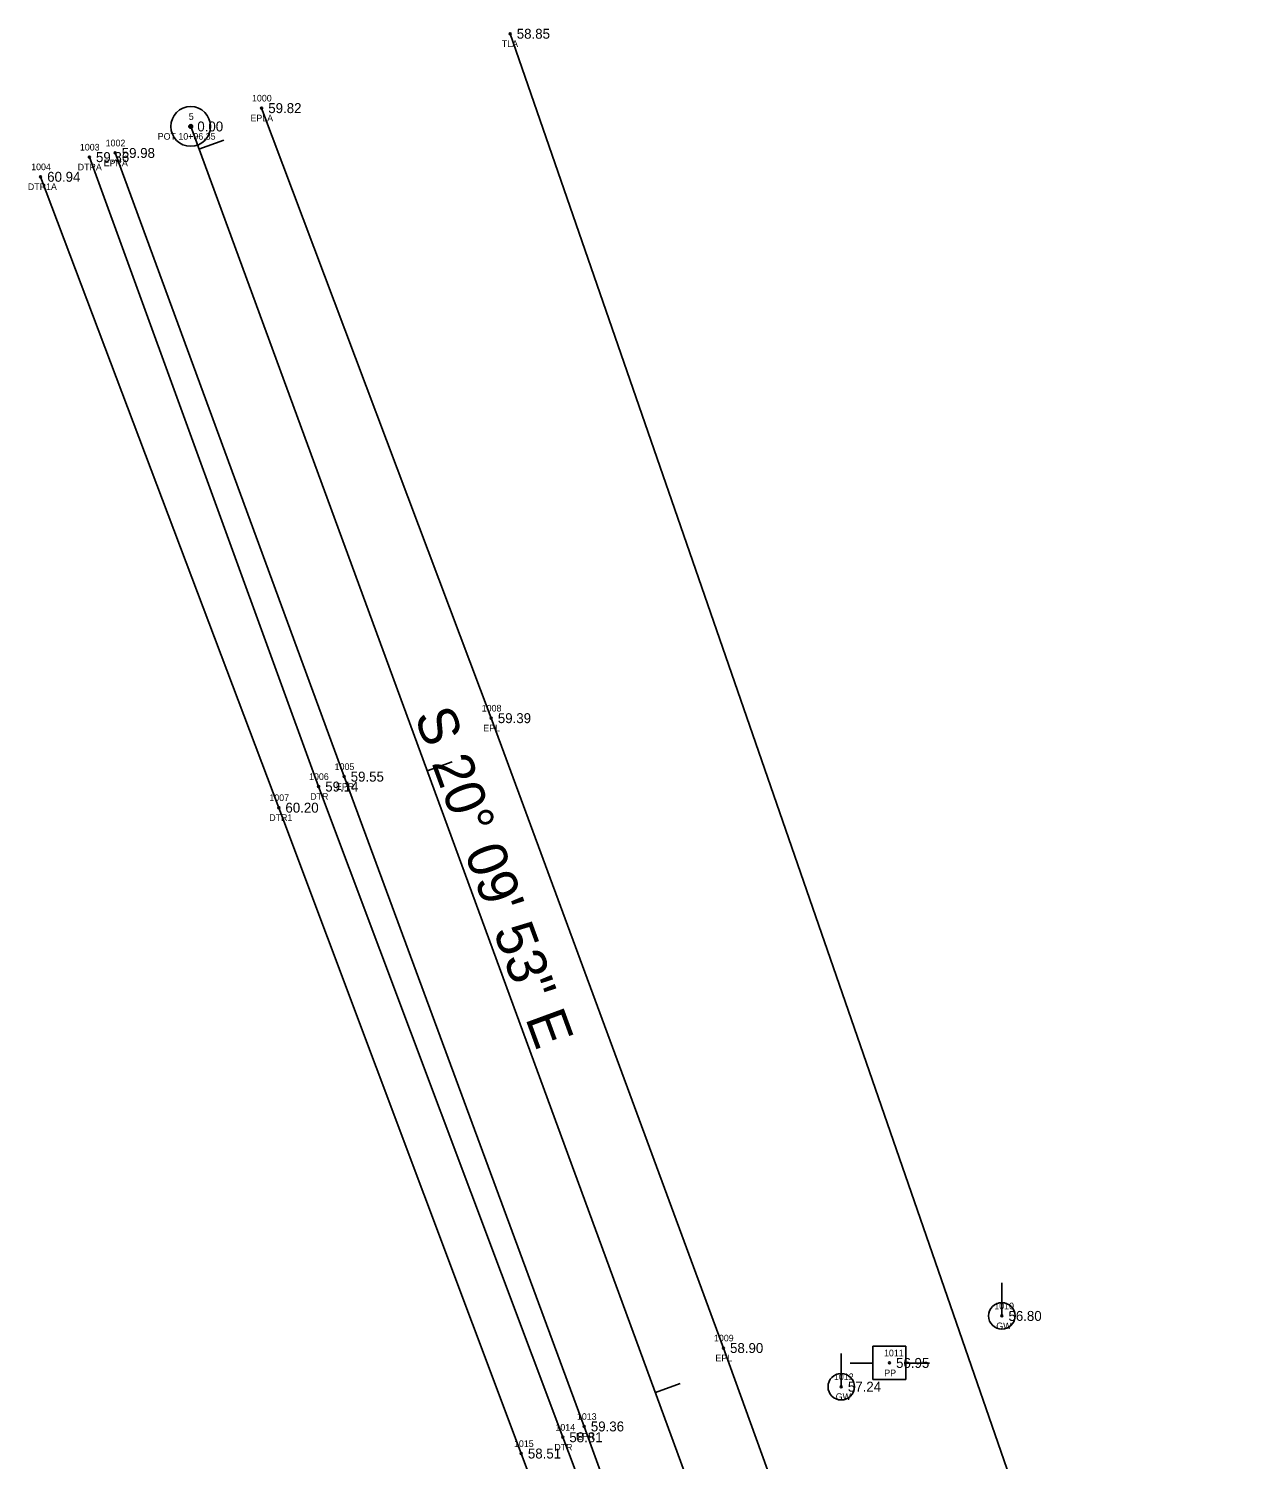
# Model space of a CAD drawing. Extents: x 2396531 to 2397633, y 770203 to 772837.
# Drawn here: x 2396645.7 to 2396831.5, y 772413.8 to 772629.8 of the extents above; entities that cross this region are included whole.
import ezdxf

# ---------------------------------------------------------------- set-up
doc = ezdxf.new("R2010")
doc.units = 0
for name, color, linetype in [('RD_EX_H2O', 7, 'Continuous'), ('RD_EX_H2O_txCode', 7, 'Continuous'), ('RD_EX_Road', 7, 'Continuous'), ('RD_EX_Road_txCode', 7, 'Continuous'), ('RD_EX_TX_H2O_ELEV', 7, 'Continuous'), ('RD_EX_TX_Road_ELEV', 7, 'Continuous'), ('RD_EX_TX_UT_ELEV', 7, 'Continuous'), ('RD_EX_TX_VEG_ELEV', 7, 'Continuous'), ('RD_EX_UT', 7, 'Continuous'), ('RD_EX_UT_txCode', 7, 'Continuous'), ('RD_EX_VEG', 7, 'Continuous'), ('RD_EX_VEG_txCode', 7, 'Continuous'), ('RD_HC_Cl', 7, 'Continuous'), ('RD_HC_Data', 7, 'Continuous'), ('RD_HC_Data_Tic', 7, 'Continuous'), ('RD_HC_Survey_ELEV', 7, 'Continuous'), ('RD_HC_txCode', 7, 'Continuous'), ('RD_SMD_Locator', 7, 'Continuous')]:
    doc.layers.add(name, color=color, linetype=linetype)

msp = doc.modelspace()

# ---------------------------------------------------------------- linework, layer by layer
at = {"layer": 'RD_EX_H2O'}
for points in [[(2396654.89, 772610.44), (2396689.53, 772515.4), (2396726.4, 772417.15), (2396758.49, 772332.26), (2396786.59, 772254.26)], [(2396647.52, 772607.47), (2396683.51, 772512.21), (2396720.14, 772414.69), (2396752.02, 772329.6), (2396778.94, 772251.31)]]:
    msp.add_lwpolyline(points, dxfattribs=at)
at = {"layer": 'RD_EX_Road'}
for points in [[(2396680.92, 772617.84), (2396715.6, 772525.73), (2396750.68, 772430.62), (2396786.3, 772332.21), (2396811.38, 772263.31), (2396839.69, 772181.74), (2396863.75, 772109.83), (2396883.63, 772046.56), (2396889.54, 772027.11), (2396896.25, 772004.37), (2396904.34, 771978.33), (2396908.24, 771964.89), (2396921.74, 771919.68), (2396927.03, 771902.11), (2396950.2, 771821.74), (2396970.47, 771750.68), (2396978.33, 771721.29), (2396990.58, 771675.04), (2397004.94, 771620.49), (2397034.26, 771508.8), (2397061.11, 771410.49), (2397060.64, 771407.04), (2397062.07, 771407.67)], [(2396658.78, 772611.07), (2396693.37, 772516.9), (2396729.65, 772418.78), (2396760.7, 772333.11), (2396788.58, 772254.87), (2396814.65, 772181.57), (2396841.1, 772100.86), (2396861.19, 772037.76), (2396886.09, 771955.71), (2396907.15, 771884.49), (2396928.56, 771811.72), (2396947.65, 771744.09), (2396985.17, 771602.64), (2397011.11, 771504.04), (2397037.95, 771404.25), (2397039, 771401.22)]]:
    msp.add_lwpolyline(points, dxfattribs=at)
at = {"layer": 'RD_EX_UT'}
for p, q in [((2396792.74, 772435.47), (2396792.74, 772440.47)), ((2396768.48, 772424.78), (2396768.48, 772429.78)), ((2396778.25, 772430.88), (2396773.25, 772430.88)), ((2396773.25, 772430.88), (2396773.25, 772425.88)), ((2396778.25, 772425.88), (2396778.25, 772430.88)), ((2396769.82, 772428.32), (2396773.28, 772428.32)), ((2396778.17, 772428.32), (2396781.82, 772428.32)), ((2396773.25, 772425.88), (2396778.25, 772425.88))]:
    msp.add_line(p, q, dxfattribs=at)
for centre in [(2396792.74, 772435.47), (2396768.48, 772424.78)]:
    msp.add_circle(centre, 2, dxfattribs=at)
at = {"layer": 'RD_EX_VEG'}
msp.add_lwpolyline([(2396718.46, 772629.07), (2396813.42, 772354.87), (2396912.88, 772043.07)], dxfattribs=at)
at = {"layer": 'RD_HC_Cl'}
msp.add_line((2396670.2, 772615.07), (2396756.43, 772380.23), dxfattribs=at)
at = {"layer": 'RD_HC_Data'}
for radius in [3, 0.282]:
    msp.add_circle((2396670.2, 772615.07), radius, dxfattribs=at)
at = {"layer": 'RD_HC_Data_Tic'}
for p, q in [((2396671.45, 772611.64), (2396675.21, 772613.02)), ((2396705.93, 772517.77), (2396709.68, 772519.15)), ((2396740.4, 772423.9), (2396744.15, 772425.28))]:
    msp.add_line(p, q, dxfattribs=at)
at = {"layer": 'RD_SMD_Locator'}
for centre in [(2396718.46, 772629.07), (2396680.92, 772617.84), (2396670.2, 772615.07), (2396654.89, 772610.44), (2396658.78, 772611.07), (2396647.52, 772607.47), (2396715.6, 772525.73), (2396689.53, 772515.4), (2396693.37, 772516.9), (2396683.51, 772512.21), (2396792.74, 772435.47), (2396750.68, 772430.62), (2396775.76, 772428.37), (2396768.48, 772424.78), (2396729.65, 772418.78), (2396726.4, 772417.15), (2396720.14, 772414.69)]:
    msp.add_circle(centre, 0.15, dxfattribs=at)

# ---------------------------------------------------------------- texts
at = {"layer": 'RD_EX_H2O_txCode'}
for s, p in [('1003', (2396653.46, 772611.44)), ('1004', (2396646.1, 772608.47)), ('DTRA', (2396653.13, 772608.44)), ('DTR1A', (2396645.6, 772605.47)), ('1006', (2396688.08, 772516.4)), ('1007', (2396682.08, 772513.21)), ('DTR', (2396688.26, 772513.4)), ('DTR1', (2396682.07, 772510.21)), ('1014', (2396725.3, 772418.15)), ('1015', (2396719.04, 772415.69)), ('DTR', (2396725.13, 772415.15))]:
    msp.add_text(s, height=1, dxfattribs=at).set_placement(p)
at = {"layer": 'RD_EX_Road_txCode'}
for s, p in [('1000', (2396679.46, 772618.84)), ('EPLA', (2396679.23, 772615.84)), ('1002', (2396657.35, 772612.07)), ('EPRA', (2396657.06, 772609.07)), ('1008', (2396714.17, 772526.73)), ('EPL', (2396714.39, 772523.73)), ('1005', (2396691.94, 772517.9)), ('EPR', (2396692.14, 772514.9)), ('1009', (2396749.25, 772431.62)), ('EPL', (2396749.47, 772428.62)), ('1013', (2396728.55, 772419.78)), ('EPR', (2396728.42, 772416.78))]:
    msp.add_text(s, height=1, dxfattribs=at).set_placement(p)
at = {"layer": 'RD_EX_TX_H2O_ELEV'}
for s, p in [('59.36', (2396655.89, 772609.69)), ('60.94', (2396648.52, 772606.72)), ('59.14', (2396690.53, 772514.65)), ('60.20', (2396684.51, 772511.46)), ('58.81', (2396727.4, 772416.4)), ('58.51', (2396721.14, 772413.94))]:
    msp.add_text(s, height=1.5, dxfattribs=at).set_placement(p)
at = {"layer": 'RD_EX_TX_Road_ELEV'}
for s, p in [('59.82', (2396681.92, 772617.09)), ('59.98', (2396659.78, 772610.32)), ('59.39', (2396716.6, 772524.98)), ('59.55', (2396694.37, 772516.15)), ('58.90', (2396751.68, 772429.87)), ('59.36', (2396730.65, 772418.03))]:
    msp.add_text(s, height=1.5, dxfattribs=at).set_placement(p)
at = {"layer": 'RD_EX_TX_UT_ELEV'}
for s, p in [('56.80', (2396793.74, 772434.72)), ('57.24', (2396769.48, 772424.03))]:
    msp.add_text(s, height=1.5, dxfattribs=at).set_placement(p)
at = {"layer": 'RD_EX_TX_VEG_ELEV'}
msp.add_text('58.85', height=1.5, dxfattribs=at).set_placement((2396719.46, 772628.32))
at = {"layer": 'RD_EX_UT_txCode'}
for s, p in [('1010', (2396791.6, 772436.47)), ('GW', (2396791.9, 772433.47)), ('1011', (2396774.94, 772429.37)), ('1012', (2396767.38, 772425.78)), ('PP', (2396774.98, 772426.37)), ('GW', (2396767.64, 772422.78))]:
    msp.add_text(s, height=1, dxfattribs=at).set_placement(p)
at = {"layer": 'RD_EX_VEG_txCode'}
msp.add_text('TLA', height=1, dxfattribs=at).set_placement((2396717.2, 772627.07))
at = {"layer": 'RD_HC_Data'}
msp.add_text('S 20%%d 09\' 53" E', height=6, rotation=290.1648, dxfattribs=at).set_placement((2396703.94, 772526.09))
at = {"layer": 'RD_HC_Survey_ELEV'}
for s, p in [('0.00', (2396671.2, 772614.32)), ('56.95', (2396776.76, 772427.62))]:
    msp.add_text(s, height=1.5, dxfattribs=at).set_placement(p)
at = {"layer": 'RD_HC_txCode'}
for s, p in [('5', (2396669.91, 772616.07)), ('POT 10+96.35', (2396665.22, 772613.07))]:
    msp.add_text(s, height=1, dxfattribs=at).set_placement(p)

doc.saveas('drawing.dxf')
